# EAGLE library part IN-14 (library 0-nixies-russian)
IN-14: medium numeric frontview nixie tube
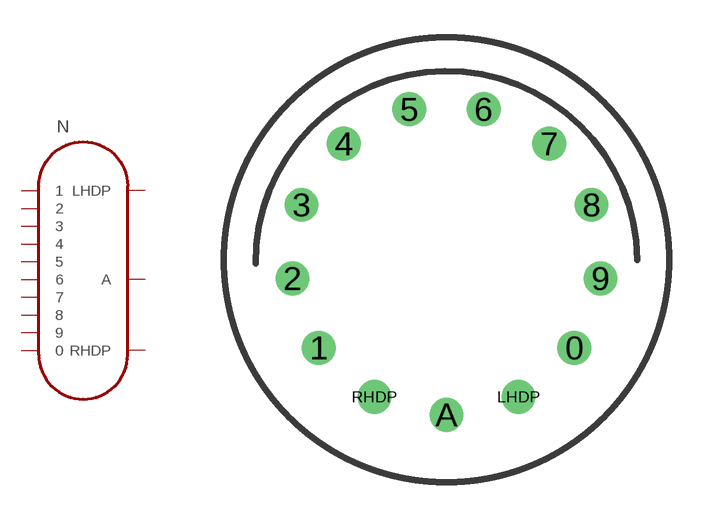
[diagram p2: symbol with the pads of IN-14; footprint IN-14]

Designator prefix N

## IN-14  [IN-14]
0  0
1  1
2  2
3  3
4  4
5  5
6  6
7  7
8  8
9  9
A  A
LHDP  LHDP
RHDP  RHDP

## Footprint IN-14 (pad centres in mm)
drill 0.84 round: 0 5.094,-3.516; 1 -5.094,-3.516; 2 -6.145,-0.746; 3 -5.788,2.195; 4 -4.105,4.633; 5 -1.481,6.01; 6 1.481,6.01; 7 4.105,4.633; 8 5.788,2.195; 9 6.145,-0.746; A 0,-6.19; LHDP 2.877,-5.481; RHDP -2.877,-5.481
